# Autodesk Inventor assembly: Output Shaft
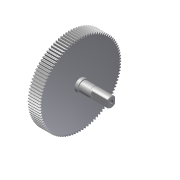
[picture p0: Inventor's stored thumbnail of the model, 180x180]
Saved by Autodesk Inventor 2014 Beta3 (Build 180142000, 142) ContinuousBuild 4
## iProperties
Created: 2011-01
Part Number: Output Shaft
Document SubType Name: Assembly
Designer: Beta-8540w
ClientObjectVersion: 1
Author: Beta-8540w
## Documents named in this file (2)
- C:\Inventor 2014 Essentials\Assemblies\Chapter 09\Design Accelerators\Shaft c09-01.iam
- C:\Inventor 2014 Essentials\Assemblies\Chapter 09\Design Accelerators\Shaft c09-01.ipt
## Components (1 placed, 1 different names)
1. Input Shaft:1
